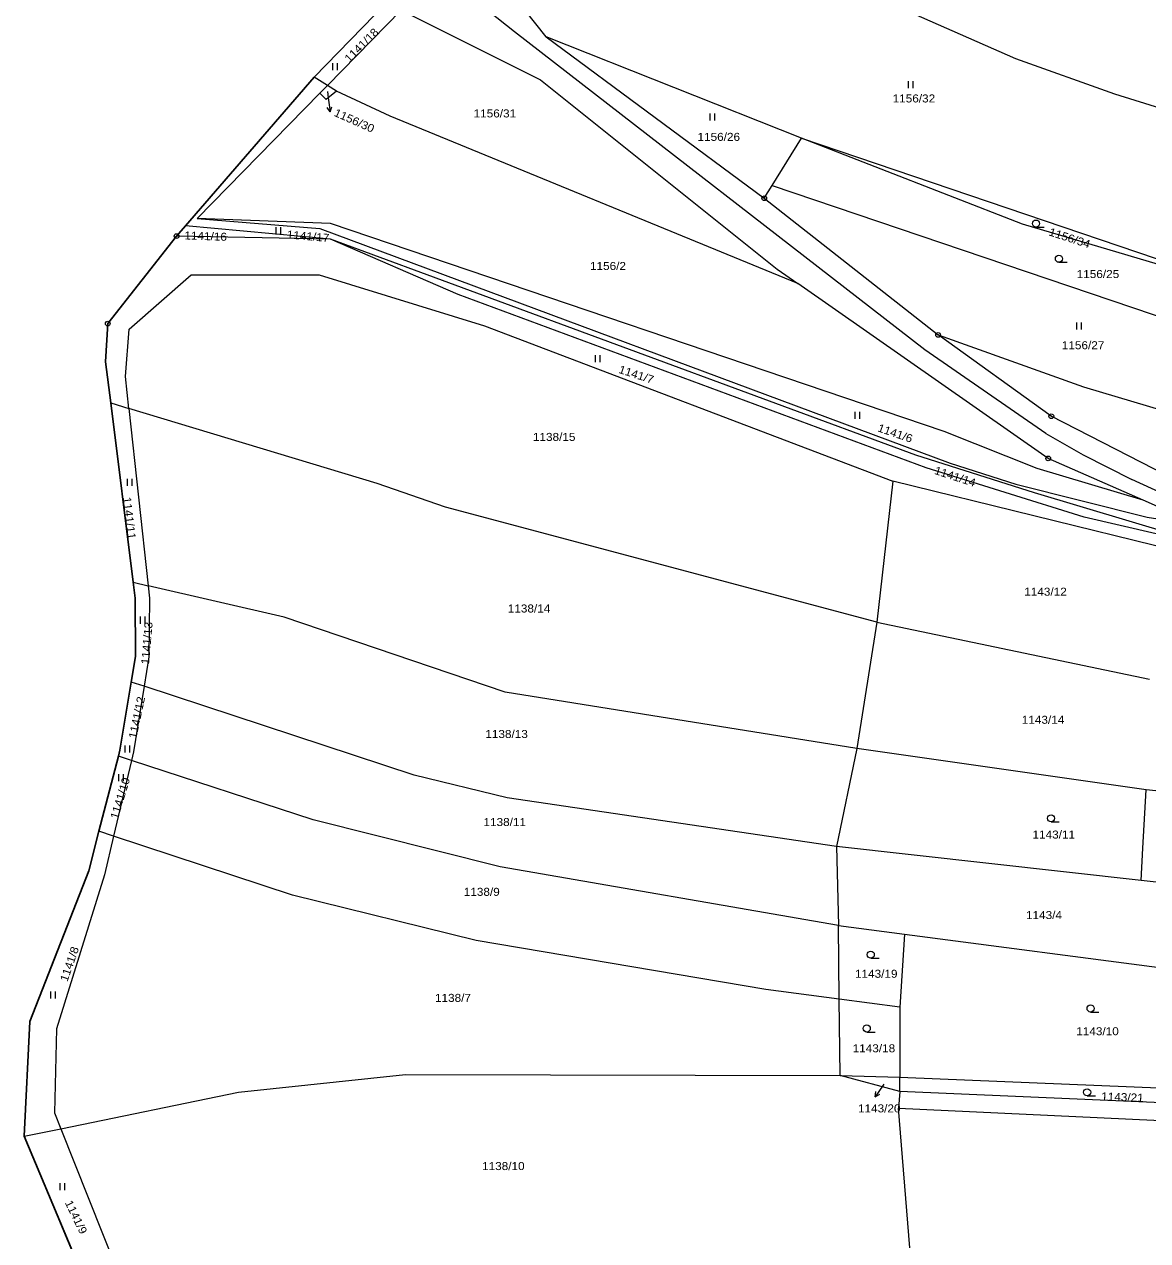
# Model space of a CAD drawing. Extents: x -686207 to -681951, y -1020493 to -1017811.
# Drawn here: x -684572.6 to -684334, y -1019323.9 to -1019065.6 of the extents above; entities that cross this region are included whole.
import ezdxf

# ---------------------------------------------------------------- set-up
doc = ezdxf.new("R2010")
doc.units = 0
doc.header["$LTSCALE"] = 0.4
for name, color, linetype, lineweight in [('1', 7, 'Continuous', 13), ('24', 7, 'Continuous', 25), ('3', 7, 'Continuous', 13), ('4', 7, 'Continuous', 13), ('6', 7, 'Continuous', 13), ('7', 7, 'Continuous', 13), ('8', 7, 'Continuous', 13)]:
    doc.layers.add(name, color=color, linetype=linetype, lineweight=lineweight)
doc.layers.add('2', color=7, linetype='Continuous')

msp = doc.modelspace()

# ---------------------------------------------------------------- linework, layer by layer
at = {"layer": '1'}
for p, q in [((-684461.78, -1019068.31), (-684472.31, -1019054.91)), ((-684511.03, -1019076.87), (-684495.69, -1019061.1)), ((-684508.21, -1019078.6), (-684492.58, -1019062.65)), ((-684407.52, -1019089.82), (-684461.78, -1019068.31)), ((-684538.37, -1019108.4), (-684511.03, -1019076.87)), ((-684508.21, -1019078.6), (-684511.03, -1019076.87)), ((-684509.81, -1019080.23), (-684508.21, -1019078.6)), ((-684506.27, -1019079.79), (-684508.21, -1019078.6)), ((-684509.81, -1019080.23), (-684535.89, -1019106.84)), ((-684413.75, -1019099.84), (-684407.52, -1019089.82)), ((-684407.52, -1019089.82), (-684305.48, -1019124.42)), ((-684413.75, -1019099.84), (-684308.39, -1019135.53)), ((-684415.44, -1019102.56), (-684378.53, -1019131.6)), ((-684540.28, -1019110.6), (-684538.37, -1019108.4)), ((-684507.56, -1019111.25), (-684538.37, -1019108.4)), ((-684507.56, -1019111.25), (-684540.28, -1019110.6)), ((-684554.27, -1019146.01), (-684550.38, -1019147.19)), ((-684549.5, -1019184.12), (-684554.27, -1019146.01)), ((-684550.38, -1019147.19), (-684546.28, -1019184.86)), ((-684388.16, -1019162.63), (-684391.53, -1019192.59)), ((-684328.11, -1019177.42), (-684388.16, -1019162.63)), ((-684322.71, -1019172.07), (-684335, -1019166.67)), ((-684549.5, -1019184.12), (-684546.28, -1019184.86)), ((-684391.53, -1019192.59), (-684395.77, -1019219.45)), ((-684391.53, -1019192.59), (-684333.66, -1019204.71)), ((-684547.17, -1019206.2), (-684549.92, -1019205.3)), ((-684395.77, -1019219.45), (-684400.12, -1019240.26)), ((-684549.84, -1019221.94), (-684553.64, -1019238.01)), ((-684549.84, -1019221.94), (-684552.63, -1019221.03)), ((-684400.12, -1019240.26), (-684399.66, -1019257.02)), ((-684399.66, -1019257.02), (-684385.64, -1019258.86)), ((-684399.51, -1019272.63), (-684399.66, -1019257.02)), ((-684385.64, -1019258.86), (-684386.67, -1019274.33)), ((-684385.64, -1019258.86), (-684314.18, -1019268.24)), ((-684386.67, -1019274.33), (-684399.51, -1019272.63)), ((-684399.35, -1019288.83), (-684399.51, -1019272.63)), ((-684399.35, -1019288.83), (-684386.68, -1019289.22)), ((-684386.68, -1019292.23), (-684399.35, -1019288.83)), ((-684386.68, -1019292.23), (-684386.92, -1019295.82)), ((-684572.61, -1019301.76), (-684564.87, -1019300.16)), ((-684558.08, -1019336.52), (-684572.61, -1019301.76)), ((-684564.87, -1019300.16), (-684551.9, -1019332.74))]:
    msp.add_line(p, q, dxfattribs=at)
for points in [[(-684441.55, -1019031.19), (-684397.84, -1019057.1), (-684390.29, -1019060.49), (-684362.1, -1019072.92), (-684341.05, -1019080.4), (-684295.11, -1019094.7)], [(-684492.58, -1019062.65), (-684462.97, -1019077.42), (-684412.71, -1019117.62), (-684408.34, -1019120.67)], [(-684461.78, -1019068.31), (-684415.44, -1019102.56), (-684413.75, -1019099.84)], [(-684506.27, -1019079.79), (-684508.49, -1019081.59), (-684509.81, -1019080.23)], [(-684408.34, -1019120.67), (-684494.88, -1019085.11), (-684506.27, -1019079.79)], [(-684305.48, -1019124.42), (-684360.57, -1019108.08), (-684407.52, -1019089.82)], [(-684335, -1019166.67), (-684357.49, -1019159.98), (-684377.26, -1019152.1), (-684507.61, -1019107.93), (-684535.89, -1019106.84)], [(-684535.89, -1019106.84), (-684509.81, -1019108.98), (-684375.93, -1019158.85), (-684362, -1019163.25), (-684334.13, -1019170.3), (-684322.71, -1019172.07)], [(-684554.27, -1019146.01), (-684555.36, -1019137.29), (-684554.88, -1019129.19), (-684540.28, -1019110.6)], [(-684317.84, -1019177.17), (-684358.07, -1019165.14), (-684383.26, -1019157.13), (-684507.56, -1019111.25)], [(-684317.84, -1019177.17), (-684347.48, -1019170.32), (-684381.05, -1019159.79), (-684480.46, -1019122.98), (-684507.56, -1019111.25)], [(-684550.38, -1019147.19), (-684551.12, -1019140.39), (-684550.33, -1019130.4), (-684537.17, -1019118.84), (-684510.02, -1019118.81), (-684474.87, -1019129.63), (-684388.16, -1019162.63)], [(-684335, -1019166.67), (-684355.14, -1019157.82), (-684408.34, -1019120.67)], [(-684378.53, -1019131.6), (-684347.63, -1019142.59), (-684312.94, -1019152.98)], [(-684303.6, -1019171.9), (-684321.66, -1019165.69), (-684354.48, -1019148.86), (-684378.53, -1019131.6)], [(-684391.53, -1019192.59), (-684483.14, -1019168.17), (-684497.64, -1019163.17), (-684550.38, -1019147.19)], [(-684549.92, -1019205.3), (-684549.02, -1019199.86), (-684549.08, -1019187.46), (-684549.5, -1019184.12)], [(-684546.28, -1019184.86), (-684545.99, -1019187.51), (-684546.17, -1019199.94), (-684547.17, -1019206.2)], [(-684395.77, -1019219.45), (-684470.48, -1019207.43), (-684517.39, -1019191.5), (-684546.28, -1019184.86)], [(-684552.63, -1019221.03), (-684552.3, -1019219.76), (-684549.92, -1019205.3)], [(-684547.17, -1019206.2), (-684549.41, -1019220.12), (-684549.84, -1019221.94)], [(-684400.12, -1019240.26), (-684470.05, -1019229.93), (-684489.79, -1019225.05), (-684547.17, -1019206.2)], [(-684326.93, -1019228.97), (-684334.37, -1019228.17), (-684395.77, -1019219.45)], [(-684553.64, -1019238.01), (-684556.76, -1019236.98), (-684552.63, -1019221.03)], [(-684399.66, -1019257.02), (-684471.54, -1019244.53), (-684511.23, -1019234.55), (-684549.84, -1019221.94)], [(-684566.48, -1019264.65), (-684558.94, -1019245.37), (-684556.76, -1019236.98)], [(-684553.64, -1019238.01), (-684555.59, -1019246.25), (-684565.78, -1019278.96), (-684566.22, -1019296.78), (-684564.87, -1019300.16)], [(-684399.51, -1019272.63), (-684415.13, -1019270.57), (-684476.61, -1019260.22), (-684515.64, -1019250.59), (-684553.64, -1019238.01)], [(-684312.81, -1019249.93), (-684335.38, -1019247.43), (-684400.12, -1019240.26)], [(-684572.61, -1019301.76), (-684571.47, -1019277.4), (-684566.48, -1019264.65)], [(-684386.67, -1019274.33), (-684386.68, -1019286.51), (-684386.68, -1019289.22)], [(-684564.87, -1019300.16), (-684527.13, -1019292.37), (-684491.62, -1019288.65), (-684399.35, -1019288.83)], [(-684309.71, -1019295.62), (-684386.68, -1019292.23), (-684386.68, -1019289.22), (-684309.4, -1019292.42)], [(-684384.55, -1019325.45), (-684386.92, -1019295.82), (-684267.9, -1019301.39)]]:
    msp.add_lwpolyline(points, dxfattribs=at)
at = {"layer": '24'}
msp.add_lwpolyline([(-684495.69, -1019061.1), (-684511.03, -1019076.87), (-684538.37, -1019108.4), (-684540.28, -1019110.6), (-684554.88, -1019129.19), (-684555.36, -1019137.29), (-684554.27, -1019146.01), (-684549.5, -1019184.12), (-684549.08, -1019187.46), (-684549.02, -1019199.86), (-684549.92, -1019205.3), (-684552.3, -1019219.76), (-684552.63, -1019221.03), (-684556.76, -1019236.98), (-684558.94, -1019245.37), (-684571.47, -1019277.4), (-684572.61, -1019301.76), (-684558.08, -1019336.52)], dxfattribs=at)
at = {"layer": '3'}
for p, q in [((-684507.071, -1019075.39), (-684507.071, -1019073.89)), ((-684506.07, -1019075.39), (-684506.07, -1019073.89)), ((-684384.791, -1019079.17), (-684384.791, -1019077.67)), ((-684383.79, -1019079.17), (-684383.79, -1019077.67)), ((-684426.931, -1019086.04), (-684426.931, -1019084.54)), ((-684425.93, -1019086.04), (-684425.93, -1019084.54)), ((-684519.151, -1019110.23), (-684519.151, -1019108.73)), ((-684518.15, -1019110.23), (-684518.15, -1019108.73)), ((-684357.743, -1019108.69), (-684355.993, -1019108.69)), ((-684352.873, -1019116.17), (-684351.123, -1019116.17)), ((-684349.051, -1019130.43), (-684349.051, -1019128.93)), ((-684348.05, -1019130.43), (-684348.05, -1019128.93)), ((-684451.311, -1019137.37), (-684451.311, -1019135.87)), ((-684450.31, -1019137.37), (-684450.31, -1019135.87)), ((-684396.131, -1019149.41), (-684396.131, -1019147.91)), ((-684395.13, -1019149.41), (-684395.13, -1019147.91)), ((-684550.671, -1019163.65), (-684550.671, -1019162.15)), ((-684549.67, -1019163.65), (-684549.67, -1019162.15)), ((-684547.911, -1019192.92), (-684547.911, -1019191.42)), ((-684546.91, -1019192.92), (-684546.91, -1019191.42)), ((-684551.191, -1019220.3), (-684551.191, -1019218.8)), ((-684550.19, -1019220.3), (-684550.19, -1019218.8)), ((-684552.561, -1019226.38), (-684552.561, -1019224.88)), ((-684551.56, -1019226.38), (-684551.56, -1019224.88)), ((-684354.533, -1019235), (-684352.783, -1019235)), ((-684392.823, -1019263.95), (-684391.073, -1019263.95)), ((-684566.991, -1019272.51), (-684566.991, -1019271.01)), ((-684565.99, -1019272.51), (-684565.99, -1019271.01)), ((-684346.143, -1019275.38), (-684344.393, -1019275.38)), ((-684393.673, -1019279.63), (-684391.923, -1019279.63)), ((-684346.873, -1019293.18), (-684345.123, -1019293.18)), ((-684565.021, -1019313.23), (-684565.021, -1019311.73)), ((-684564.02, -1019313.23), (-684564.02, -1019311.73))]:
    msp.add_line(p, q, dxfattribs=at)
for centre in [(-684357.7429, -1019107.9398), (-684352.8729, -1019115.4198), (-684354.5329, -1019234.2498), (-684392.8229, -1019263.1998), (-684346.1429, -1019274.6298), (-684393.6729, -1019278.8798), (-684346.8729, -1019292.4298)]:
    msp.add_circle(centre, 0.75, dxfattribs=at)
at = {"layer": '4'}
for p, q in [((-684335.03, -1019240.61), (-684334.37, -1019228.17)), ((-684335.38, -1019247.43), (-684335.03, -1019240.61))]:
    msp.add_line(p, q, dxfattribs=at)
at = {"layer": '6'}
for p, q in [((-684468.49, -1019067.2), (-684484.23, -1019054.75)), ((-684381.38, -1019134.79), (-684468.49, -1019067.2)), ((-684355.64, -1019152.52), (-684381.38, -1019134.79)), ((-684355.64, -1019152.52), (-684347.69, -1019157.09)), ((-684347.69, -1019157.09), (-684337.35, -1019162.32)), ((-684322.79, -1019168.97), (-684337.35, -1019162.32))]:
    msp.add_line(p, q, dxfattribs=at)
at = {"layer": '7'}
for p, q in [((-684507.642, -1019084.232), (-684507.286, -1019083.17)), ((-684390.05, -1019290.71), (-684390.19, -1019290.91)), ((-684391.911, -1019293.368), (-684390.927, -1019292.835))]:
    msp.add_line(p, q, dxfattribs=at)
for points in [[(-684508.25, -1019079.89), (-684508.06, -1019081.26), (-684507.642, -1019084.232), (-684508.278, -1019083.31)], [(-684390.19, -1019290.91), (-684391.911, -1019293.368), (-684391.747, -1019292.261)]]:
    msp.add_lwpolyline(points, dxfattribs=at)
at = {"layer": '8'}
for centre, radius in [((-684415.44, -1019102.5599), 0.5), ((-684415.44, -1019102.5599), 0.0303), ((-684540.28, -1019110.5999), 0.5), ((-684540.28, -1019110.5999), 0.0303), ((-684554.88, -1019129.1899), 0.5), ((-684554.88, -1019129.1899), 0.0303), ((-684378.53, -1019131.5999), 0.5), ((-684378.53, -1019131.5999), 0.0303), ((-684354.48, -1019148.8599), 0.5), ((-684354.48, -1019148.8599), 0.0303), ((-684355.14, -1019157.8199), 0.5), ((-684355.14, -1019157.8199), 0.0303)]:
    msp.add_circle(centre, radius, dxfattribs=at)

# ---------------------------------------------------------------- texts
at = {"layer": '2', "width": 1.1}
for s, rotation, p in [('1141/18', 45, (-684503.598, -1019073.861)), ('1156/30', 336, (-684507.005, -1019085.006)), ('1141/16', 358, (-684538.639, -1019111.299)), ('1141/17', 355, (-684516.924, -1019111.076)), ('1156/34', 342, (-684355.152, -1019110.408)), ('1141/7', 342, (-684446.522, -1019139.618)), ('1141/6', 341, (-684391.526, -1019152.023)), ('1141/14', 342, (-684379.472, -1019161.078)), ('1141/11', 277, (-684551.683, -1019166.103)), ('1141/13', 85, (-684546.133, -1019201.624)), ('1141/12', 78, (-684548.828, -1019217.446)), ('1141/10', 73, (-684552.767, -1019234.558)), ('1141/8', 71, (-684563.466, -1019269.086)), ('1143/21', 358, (-684343.909, -1019294.139)), ('1141/9', 296, (-684564.053, -1019315.862))]:
    msp.add_text(s, height=1.7, rotation=rotation, dxfattribs=at).set_placement(p)
for s, p in [('1156/32', (-684388.19, -1019082.22)), ('1156/31', (-684477.19, -1019085.4)), ('1156/26', (-684429.63, -1019090.38)), ('1156/2', (-684452.47, -1019117.799)), ('1156/25', (-684349.1, -1019119.51)), ('1156/27', (-684352.25, -1019134.63)), ('1138/15', (-684464.59, -1019154.1)), ('1143/12', (-684360.238, -1019186.97)), ('1138/14', (-684469.93, -1019190.539)), ('1143/14', (-684360.758, -1019214.169)), ('1138/13', (-684474.7, -1019217.19)), ('1138/11', (-684475.09, -1019235.89)), ('1143/11', (-684358.478, -1019238.549)), ('1138/9', (-684479.28, -1019250.71)), ('1143/4', (-684359.865, -1019255.64)), ('1143/19', (-684396.19, -1019268.11)), ('1138/7', (-684485.39, -1019273.23)), ('1143/10', (-684349.19, -1019280.32)), ('1143/18', (-684396.68, -1019283.94)), ('1143/20', (-684395.55, -1019296.7)), ('1138/10', (-684475.39, -1019308.95))]:
    msp.add_text(s, height=1.7, dxfattribs=at).set_placement(p)

doc.saveas('drawing.dxf')
